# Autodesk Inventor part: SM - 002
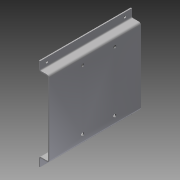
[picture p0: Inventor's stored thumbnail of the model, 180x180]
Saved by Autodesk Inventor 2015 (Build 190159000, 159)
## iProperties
Company: Autodesk, Inc.
Created: 2007-02
Part Number: SM - 002
Material: Steel
Document SubType Name: Sheet Metal
Designer: Autodesk, Inc.
Mass: 1795.98 g
Surface Area: 1540.61 cm^2
Volume: 228.787 cm^3
Density: 7.85 g/cm^3
Description: Motor Mount Base
Sheet Metal Rule: Default
Appearance: Steel
Author: Autodesk, Inc.
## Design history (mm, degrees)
node "Contour Flange1"
  sketch "Sketch1"
    geometry: L1 (6.096, 0)-(6.096, 850) reference; L2 (6.096, 752.524)-(6.096, 727.124); L3 (6.096, 727.124)-(31.496, 727.124); L4 (31.496, 727.124)-(31.496, 523.924); L5 (31.496, 523.924)-(6.096, 523.924); L6 (6.096, 523.924)-(6.096, 498.524)
    constraints: 9 end point, 3 perpendicular, 3 point on line
    dimensions: "d1" = 25.4 distance of L2.end L3.end; "d3" = 25.4 distance of L6.end L5.end (= d2)
hole "Hole1" diameter "d19" = 6.7564; stored, may be unused: countersink angle "d23" = 82 deg, drill point angle "d25" = 118 deg; dims "d17" = 11.43, "d18" = 19.05, "d20" = 12.7, "d21" = 12.8778, "d22" = 6.35, "d24" = 3.048 (= Thickness)
hole "Hole2" diameter "d28" = 6.7564; stored, may be unused: countersink angle "d32" = 82 deg, drill point angle "d34" = 118 deg; dims "d26" = 19.05, "d27" = 11.43, "d29" = 12.7, "d30" = 12.8778, "d31" = 6.35, "d33" = 3.048 (= Thickness)
pattern_linear "Rectangular Pattern1" dims "d37" = 215.9
pattern_linear "Rectangular Pattern2" dims "d40" = 215.9
sketch "Sketch4"
  geometry: 1 further point
hole "Hole4" sketch "Sketch4" at (161.646, 181.825) diameter "d48" = 8.382; stored, may be unused: countersink angle "d52" = 82 deg, drill point angle "d54" = 0 deg; dims "d49" = 12.7, "d50" = 9.525, "d51" = 6.35, "d53" = 19.05
sketch "Sketch5"
  geometry: 1 further point
hole "Hole5" sketch "Sketch5" at (72.746, 181.825) diameter "d55" = 8.382; stored, may be unused: countersink angle "d59" = 82 deg, drill point angle "d61" = 0 deg; dims "d56" = 12.7, "d57" = 9.525, "d58" = 6.35, "d60" = 19.05
sketch "Sketch6"
  geometry: 1 further point
hole "Hole6" sketch "Sketch6" at (161.646, 16.725) diameter "d62" = 8.382; stored, may be unused: countersink angle "d66" = 82 deg, drill point angle "d68" = 0 deg; dims "d63" = 12.7, "d64" = 9.525, "d65" = 6.35, "d67" = 19.05
sketch "Sketch7"
  geometry: 1 further point
hole "Hole7" sketch "Sketch7" at (72.746, 16.725) diameter "d69" = 8.382; stored, may be unused: countersink angle "d73" = 82 deg, drill point angle "d75" = 0 deg; dims "d70" = 12.7, "d71" = 9.525, "d72" = 6.35, "d74" = 19.05
body "Solid1"
node "Reference1"
face "Plate1" dims "d4" = 3.048 (= BendReliefWidth), "d5" = 1.524 (= BendReliefDepth), "d6" = 6.096 (= MinimumRemnant), "d7" = 3.048 (= BendRadius), "d8" = 254, "d9" = 3.048 (= BendRadius), "d10" = 3.048, "d11" = 12.192 (= CornerReliefSize), "d12" = 3.048 (= Thickness), "d76" = 3.048 (= JacobiRadiusSize), "SeamGap" = 0.00508, "Thickness" = 3.048
bend "Bend1" dims "d4" = 3.048 (= BendReliefWidth), "d5" = 1.524 (= BendReliefDepth), "d6" = 6.096 (= MinimumRemnant), "d7" = 3.048 (= BendRadius), "d9" = 3.048 (= BendRadius), "d10" = 3.048, "SeamGap" = 0.00508, "Thickness" = 3.048
feature "Corner1" dims "d10" = 3.048, "d11" = 12.192 (= CornerReliefSize), "d12" = 3.048 (= Thickness), "d76" = 3.048 (= JacobiRadiusSize)
other parameters: "BendRadius" = 3.048 (= Thickness), "BendReliefWidth" = 3.048 (= Thickness), "BendReliefDepth" = 1.524 (= 0.5 x Thickness), "CornerReliefSize" = 12.192 (= 4 x Thickness), "MinimumRemnant" = 6.096 (= 2 x Thickness), "TransitionRadius" = 3.048 (= BendRadius), "JacobiRadiusSize" = 3.048 (= Thickness), "d0" = 254, "d2" = 25.4, "GapSize" = 3.048 (= Thickness)
